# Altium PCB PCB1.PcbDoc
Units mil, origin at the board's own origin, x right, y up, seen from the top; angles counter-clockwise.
Board outline 12000 x 2250 mil, 2 copper layers (Top Layer 1, Bottom Layer 1), stack 62 mil thick; 28 components, 18 nets, 56 pads, 0 vias.
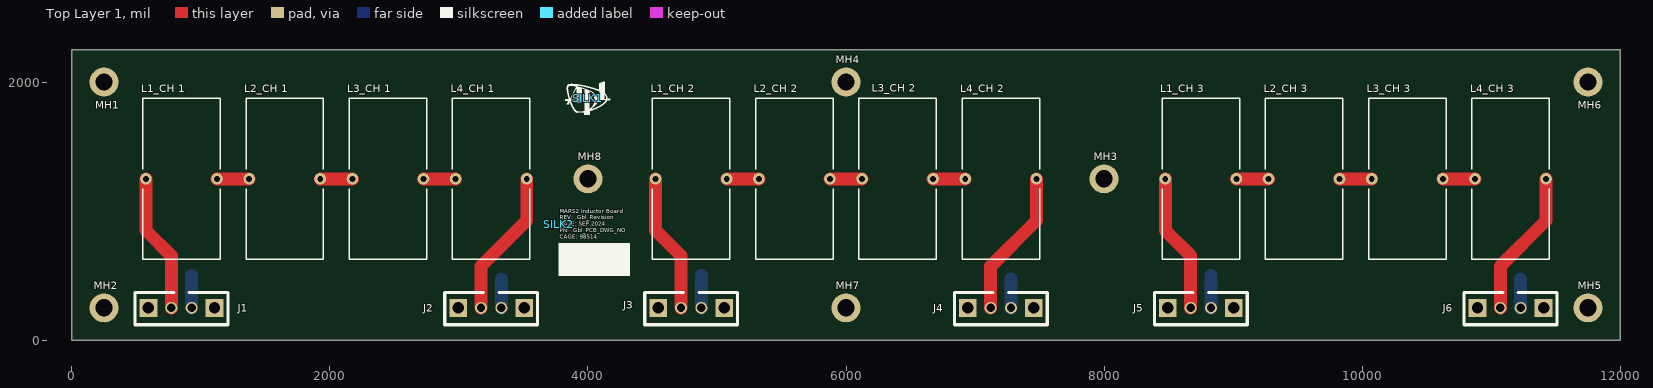
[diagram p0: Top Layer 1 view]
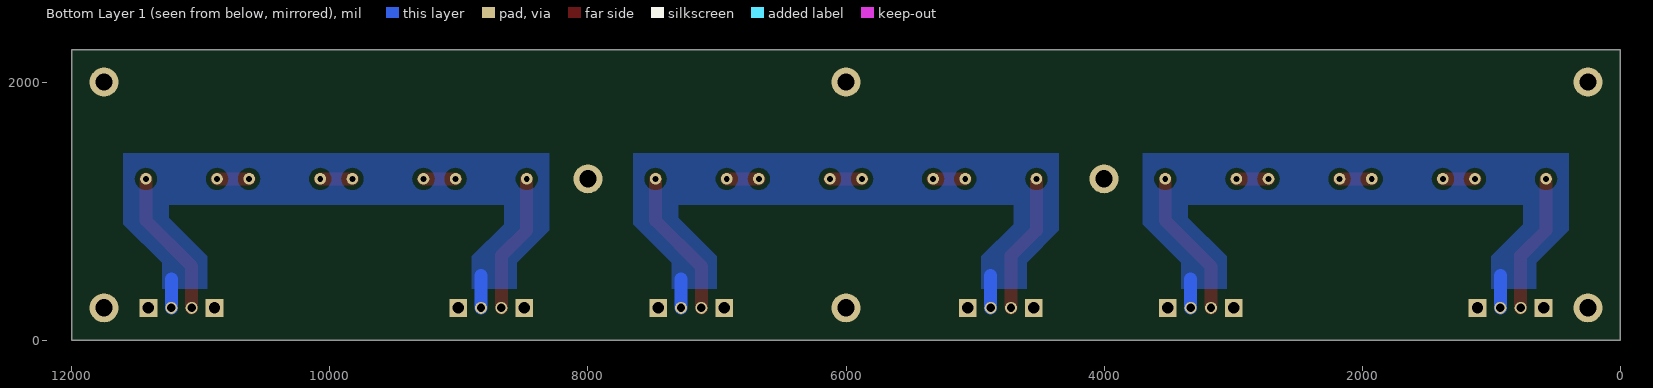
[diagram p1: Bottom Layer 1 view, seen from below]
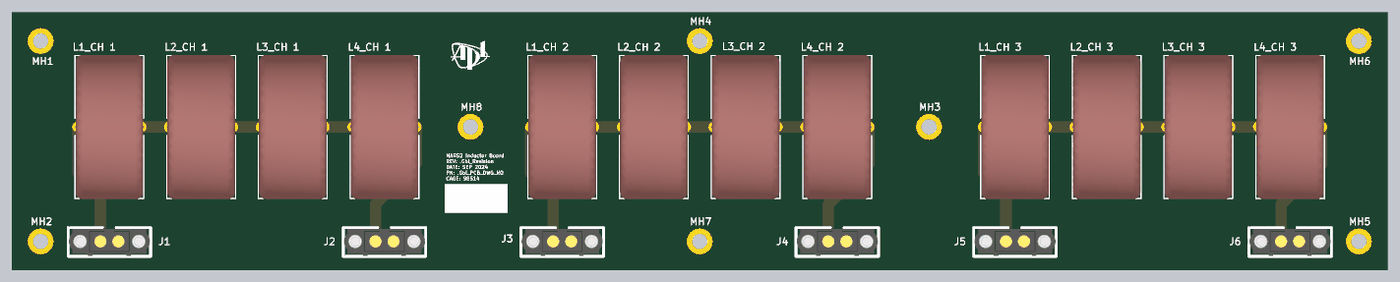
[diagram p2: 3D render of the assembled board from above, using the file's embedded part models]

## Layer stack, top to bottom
Top Solder: solder mask 0.4, Solder Resist, Dk 3.5
Top Layer 1: signal copper 1.7
Dielectric 1: dielectric 58.6, FR-4, Dk 4.8
Bottom Layer 1: signal copper 1.7
Bottom Solder: solder mask 0.4, Solder Resist, Dk 3.5

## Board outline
0,0 12000,0 12000,2250 0,2250

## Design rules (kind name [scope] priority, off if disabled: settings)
BoardOutlineClearance [All] p1: gap=10 ignorepadtopadclearanceinfootprint=FALSE
Clearance [All] p1: gap=40 ignorepadtopadclearanceinfootprint=TRUE
HoleSize [All] p1: absolutevalues=TRUE maxlimit=250 minlimit=10 maxpercent=80.000 minpercent=20.000
HoleToHoleClearance [All] p1: gap=25 allowstackedmicrovias=FALSE
MinimumAnnularRing [All] p1: minimumring=10
PolygonConnect [All] p1: connectstyle=Relief reliefconductorwidth=10 reliefentries=4 polygonreliefangle="90 Angle" airgapwidth=10
RoutingVias RoutingVias_Class3_External [All] p1: holewidth=30 width=110 viastyle="Through Hole" minholewidth=16 minwidth=96 maxholewidth=60 maxwidth=140
SolderMaskExpansion [All] p1: expansion=2.5 istentingtop=FALSE
Width [All] p1: maxlimit=250 minlimit=15 preferedwidth=20
28 further rules are at their usual default settings.

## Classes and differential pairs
channel class Channel: "CH 1" "CH 2" "CH 3"
component class "CH 3": "L1_CH 3" "L2_CH 3" "L3_CH 3" "L4_CH 3"
component class "CH 2": "L1_CH 2" "L2_CH 2" "L3_CH 2" "L4_CH 2"
component class "CH 1": "L1_CH 1" "L2_CH 1" "L3_CH 1" "L4_CH 1"
component class Top: J1 J2 J3 J4 J5 J6 MH1 MH2 MH3 MH4 MH5 MH6 MH7 MH8 SILK1 SILK2

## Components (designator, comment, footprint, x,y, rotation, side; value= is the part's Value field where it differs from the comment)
J1 "M80-5000000M2-02-331-00-000" M80-5000000M2-02-331-00-000-Footprint-1 771.26,250 r0 top
J2 "M80-5000000M2-02-331-00-000" M80-5000000M2-02-331-00-000-Footprint-1 3171.26,250 r0 top
J3 "M80-5000000M2-02-331-00-000" M80-5000000M2-02-331-00-000-Footprint-1 4721.26,250 r0 top
J4 "M80-5000000M2-02-331-00-000" M80-5000000M2-02-331-00-000-Footprint-1 7121.26,250 r0 top
J5 "M80-5000000M2-02-331-00-000" M80-5000000M2-02-331-00-000-Footprint-1 8671.26,250 r0 top
J6 "M80-5000000M2-02-331-00-000" M80-5000000M2-02-331-00-000-Footprint-1 11071.26,250 r0 top
"L1_CH 1" "ED0006-AL" ED0006-AL-Footprint-1 850,1250 r0 top (schematic designator L1)
"L1_CH 2" "ED0006-AL" ED0006-AL-Footprint-1 4800,1250 r0 top (schematic designator L1)
"L1_CH 3" "ED0006-AL" ED0006-AL-Footprint-1 8750,1250 r0 top (schematic designator L1)
"L2_CH 1" "ED0006-AL" ED0006-AL-Footprint-1 1650,1250 r0 top (schematic designator L2)
"L2_CH 2" "ED0006-AL" ED0006-AL-Footprint-1 5600,1250 r0 top (schematic designator L2)
"L2_CH 3" "ED0006-AL" ED0006-AL-Footprint-1 9550,1250 r0 top (schematic designator L2)
"L3_CH 1" "ED0006-AL" ED0006-AL-Footprint-1 2450,1250 r0 top (schematic designator L3)
"L3_CH 2" "ED0006-AL" ED0006-AL-Footprint-1 6400,1250 r0 top (schematic designator L3)
"L3_CH 3" "ED0006-AL" ED0006-AL-Footprint-1 10350,1250 r0 top (schematic designator L3)
"L4_CH 1" "ED0006-AL" ED0006-AL-Footprint-1 3250,1250 r0 top (schematic designator L4)
"L4_CH 2" "ED0006-AL" ED0006-AL-Footprint-1 7200,1250 r0 top (schematic designator L4)
"L4_CH 3" "ED0006-AL" ED0006-AL-Footprint-1 11150,1250 r0 top (schematic designator L4)
MH1 "MH-MARS2-6-32" MH-M3-Footprint-1 250,2000 r0 top
MH2 "MH-MARS2-6-32" MH-M3-Footprint-1 250,250 r0 top
MH3 "MH-MARS2-6-32" MH-M3-Footprint-1 8000,1250 r0 top
MH4 "MH-MARS2-6-32" MH-M3-Footprint-1 6000,2000 r0 top
MH5 "MH-MARS2-6-32" MH-M3-Footprint-1 11750,250 r0 top
MH6 "MH-MARS2-6-32" MH-M3-Footprint-1 11750,2000 r0 top
MH7 "MH-MARS2-6-32" MH-M3-Footprint-1 6000,250 r0 top
MH8 "MH-MARS2-6-32" MH-M3-Footprint-1 4000,1250 r0 top
SILK1 "APL Logo Silkscreen" "APL Logo Silkscreen-Footprint-1" 4000,1875 r0 top
SILK2 "APL Information Silkscreen" "APL Information Silk" 3775,900 r0 top

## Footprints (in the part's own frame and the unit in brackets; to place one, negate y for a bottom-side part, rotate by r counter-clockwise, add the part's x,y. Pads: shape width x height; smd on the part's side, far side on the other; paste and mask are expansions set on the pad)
"APL Information Silk" [mil] "General PCB information silkscreen with serial number box."
  silkscreen extent 0,-400 550,-150
"APL Logo Silkscreen-Footprint-1" [mil]
  silkscreen extent -176,-127 174,128
ED0006-AL-Footprint-1 [mil]
  round 90 hole 45.67: 1(-275.59,0) 2(275.59,0)
  silkscreen extent -300,-625 300,625, body extent -295,-630 295,630, height 1279
M80-5000000M2-02-331-00-000-Footprint-1 [mm]
  round 2.362 hole 1.65: A(0,0) B(4,0)
  rect 3.5x3.5 hole 2.25: MP1(8.5,0) MP2(-4.5,0)
  silkscreen extent -7.14,-3.3 11.14,3.05, body extent -6.99,-3.27 10.99,2.78, height 5.61
MH-M3-Footprint-1 [mm]
  round 5.7 hole 3.4: 1(0,0)

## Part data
J1 J2 J3 J4 J5 J6: library part CMP-002-00145-6, "Conn Datamate M 2Power POS 4mm Solder ST Thru-Hole Tube", Current Rating=20A, Manufacturer=Harwin, Max Operating Temperature=125°C, Min Operating Temperature=-55°C, Voltage Rating=800V
"L1_CH 1" "L1_CH 2" "L1_CH 3" "L2_CH 1" "L2_CH 2" "L2_CH 3" "L3_CH 1" "L3_CH 2" "L3_CH 3" "L4_CH 1" "L4_CH 2" "L4_CH 3": library part CMP-006-00101-2, "Power inductor, 20uH Toroidal, 20% tol, RoHS", Current Rating=7.2A, DC Resistance (DCR)=42mOhms, Inductance=20uH, Inductance Tolerance=20%, Manufacturer=CoilCraft, Max Operating Temperature=-40C, Min Operating Temperature=+125C, Saturation Current=36.0, Self Resonant Frequency=13MHz
MH1 MH2 MH3 MH4 MH5 MH6 MH7 MH8: library part CMP-00028-00015-2, "MARS2 Project 6-32 Mounting Hole Plated ."
SILK1: library part CMP-001-0033-3, "APL Logo silkscreen"
SILK2: library part CMP-001-0034-1, "Text/Box for silkscreen display of PCB information."

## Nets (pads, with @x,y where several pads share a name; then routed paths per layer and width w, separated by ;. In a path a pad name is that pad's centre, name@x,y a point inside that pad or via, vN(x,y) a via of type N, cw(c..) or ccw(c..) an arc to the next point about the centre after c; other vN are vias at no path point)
NetJ1_A: "L1_CH 1.1" J1.A | length 1081.5
  Top Layer 1 w100: 574.41,1250 575,1249.41 575,850 771.26,653.74 J1.A
NetJ1_B: J1.B J2.B | length 475
  Bottom Layer 1 w100: J1.B 928.74,500 ; J2.B 3328.74,475
NetJ2_A: "L4_CH 1.2" J2.A | length 1146.8
  Top Layer 1 w100: J2.A 3171.26,572.84 3525.59,927.16 3525.59,1250
NetJ3_A: "L1_CH 2.1" J3.A | length 1081.5
  Top Layer 1 w100: 4524.41,1250 4525,1249.41 4525,850 4721.26,653.74 J3.A
NetJ3_B: J3.B J4.B | length 475
  Bottom Layer 1 w100: J3.B 4878.74,500 ; J4.B 7278.74,475
NetJ4_A: "L4_CH 2.2" J4.A | length 1146.8
  Top Layer 1 w100: J4.A 7121.26,572.84 7475.59,927.16 7475.59,1250
NetJ5_A: "L1_CH 3.1" J5.A | length 1081.5
  Top Layer 1 w100: 8474.41,1250 8475,1249.41 8475,850 8671.26,653.74 J5.A
NetJ5_B: J5.B J6.B | length 475
  Bottom Layer 1 w100: J5.B 8828.74,500 ; J6.B 11228.74,475
NetJ6_A: "L4_CH 3.2" J6.A | length 1146.8
  Top Layer 1 w100: J6.A 11071.26,572.84 11425.59,927.16 11425.59,1250
"NetL1_CH 1_2": "L1_CH 1.2" "L2_CH 1.1" | length 248.8
  Top Layer 1 w100: 1125.59,1250 1374.41,1250
"NetL1_CH 2_2": "L1_CH 2.2" "L2_CH 2.1" | length 248.8
  Top Layer 1 w100: 5075.59,1250 5324.41,1250
"NetL1_CH 3_2": "L1_CH 3.2" "L2_CH 3.1" | length 248.8
  Top Layer 1 w100: 9025.59,1250 9274.41,1250
"NetL2_CH 1_2": "L2_CH 1.2" "L3_CH 1.1" | length 248.8
  Top Layer 1 w100: 1925.59,1250 2174.41,1250
"NetL2_CH 2_2": "L2_CH 2.2" "L3_CH 2.1" | length 248.8
  Top Layer 1 w100: 5875.59,1250 6124.41,1250
"NetL2_CH 3_2": "L2_CH 3.2" "L3_CH 3.1" | length 248.8
  Top Layer 1 w100: 9825.59,1250 10074.41,1250
"NetL3_CH 1_2": "L3_CH 1.2" "L4_CH 1.1" | length 248.8
  Top Layer 1 w100: 2725.59,1250 2974.41,1250
"NetL3_CH 2_2": "L3_CH 2.2" "L4_CH 2.1" | length 248.8
  Top Layer 1 w100: 6675.59,1250 6924.41,1250
"NetL3_CH 3_2": "L3_CH 3.2" "L4_CH 3.1" | length 248.8
  Top Layer 1 w100: 10625.59,1250 10874.41,1250
pads on no net: J1.MP1 J1.MP2 J2.MP1 J2.MP2 J3.MP1 J3.MP2 J4.MP1 J4.MP2 J5.MP1 J5.MP2 J6.MP1 J6.MP2 MH1.1 MH2.1 MH3.1 MH4.1 MH5.1 MH6.1 MH7.1 MH8.1

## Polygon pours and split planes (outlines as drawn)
NetJ5_B on Bottom Layer 1 "Bottom Layer 1-NetJ5_B" (solid, pour order 10): 11300,600 11600,900 11600,1450 8300,1450 8300,850 8550,600 8550,400 8900,400 8900,650 8650,900 8650,1050 11250,1050 11250,950 10950,650 10950,400 11300,400
NetJ3_B on Bottom Layer 1 "Bottom Layer 1-NetJ3_B" (solid, pour order 9): 7350,600 7650,900 7650,1450 4350,1450 4350,850 4600,600 4600,400 4950,400 4950,650 4700,900 4700,1050 7300,1050 7300,950 7000,650 7000,400 7350,400
NetJ1_B on Bottom Layer 1 "Bottom Layer 1-NetJ1_B" (solid, pour order 5): 3400,600 3700,900 3700,1450 400,1450 400,850 650,600 650,400 1000,400 1000,650 750,900 750,1050 3350,1050 3350,950 3050,650 3050,400 3400,400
